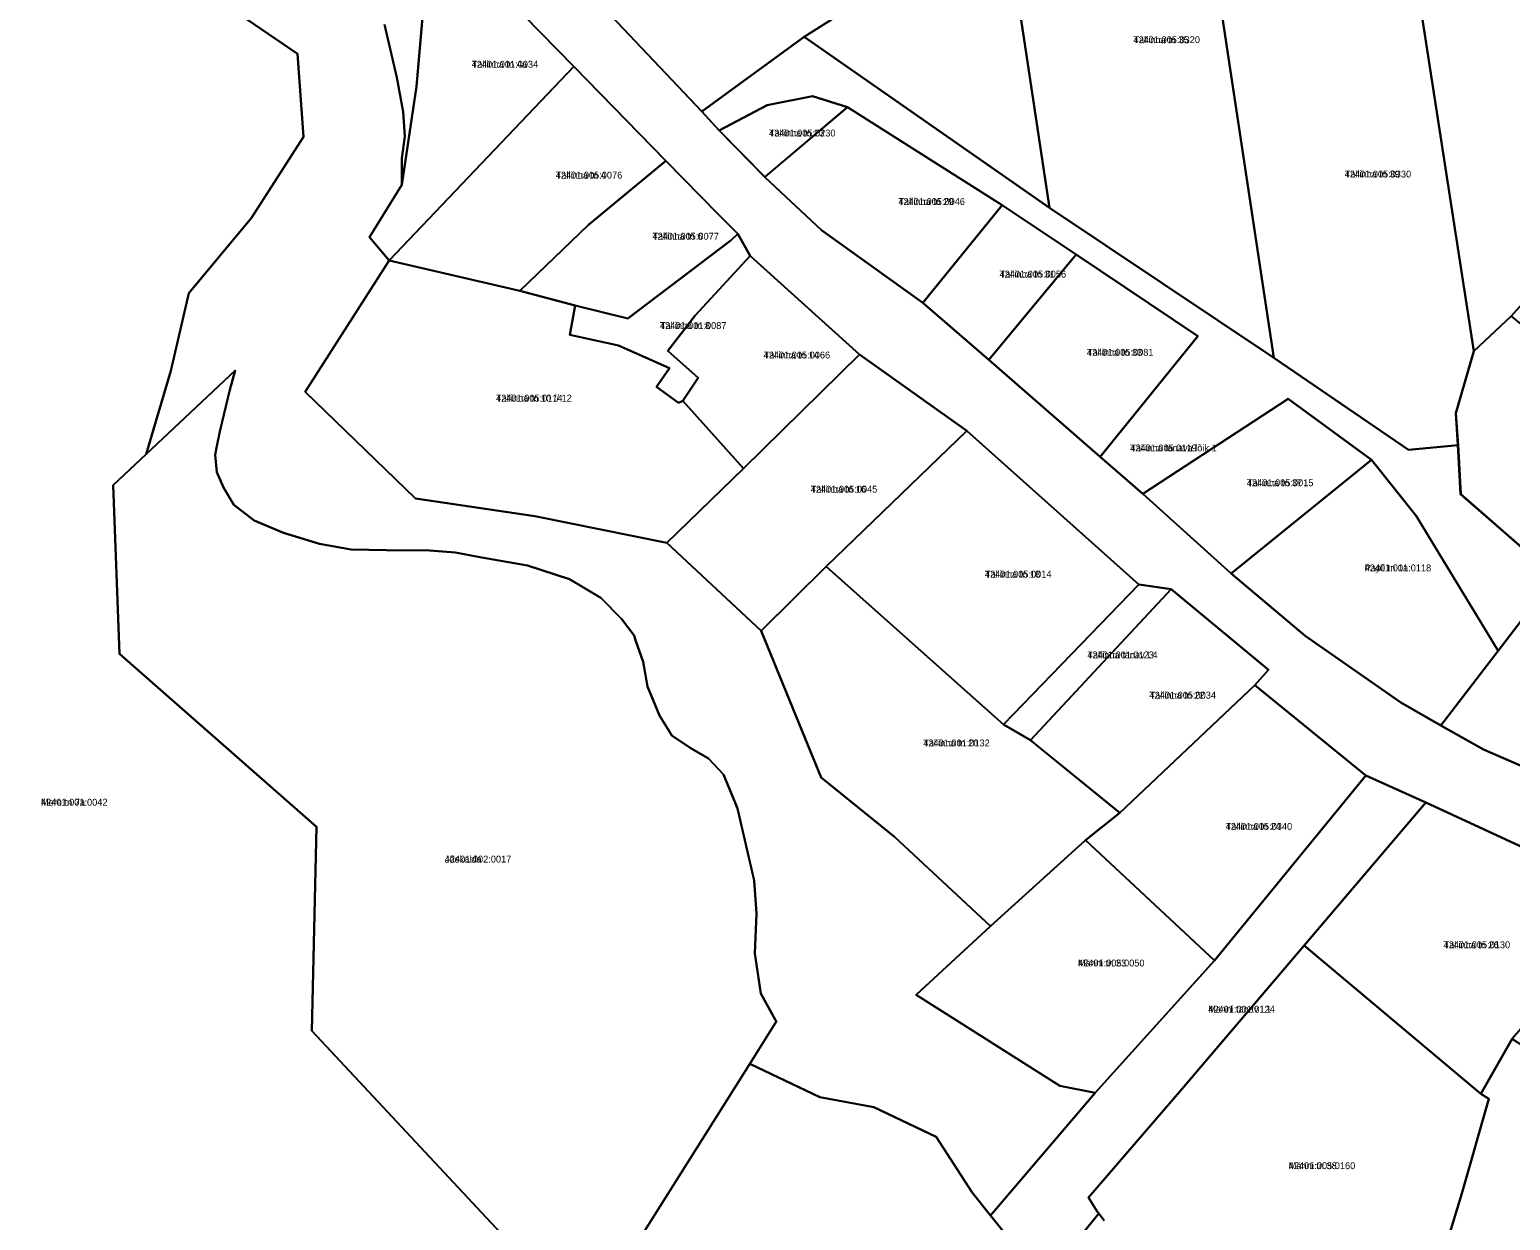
# Model space of a CAD drawing. Extents: x 595979 to 597983, y 6604231 to 6607350.
# Drawn here: x 596873.6 to 597196.3, y 6606049.7 to 6606309.2 of the extents above; entities that cross this region are included whole.
import ezdxf

# ---------------------------------------------------------------- set-up
doc = ezdxf.new("R2010")
doc.units = 0
for name, color, linetype in [('L_AADRESS', 7, 'Continuous'), ('PIIR', 7, 'Continuous'), ('TUNNUS', 7, 'Continuous')]:
    doc.layers.add(name, color=color, linetype=linetype)

msp = doc.modelspace()

# ---------------------------------------------------------------- linework, layer by layer
at = {"layer": 'PIIR'}
for points in [[(596834.39, 6606472.9), (596889.22, 6606422.58), (596903.83, 6606409.45), (596924.96, 6606390.98), (596925.76, 6606392.61), (596951.48, 6606366.75), (597000.4, 6606312.1), (597020.14, 6606291.3), (597023.9, 6606287.2), (597033.87, 6606277.01), (597046.17, 6606265.47), (597068.29, 6606249.61), (597082.64, 6606237.21), (597106.96, 6606216.02), (597116.23, 6606207.98), (597135.48, 6606190.61), (597151.62, 6606177.02), (597172.5, 6606162.53), (597181.22, 6606157.49), (597190.5, 6606152.27), (597213.06, 6606142.48)], [(597335.48, 6606042.99), (597280.71, 6606085.45), (597282.61, 6606087.75), (597275.71, 6606093.22), (597238.19, 6606110.46), (597218.63, 6606121.93), (597177.93, 6606140.7), (597164.82, 6606146.62), (597140.63, 6606166.31), (597143.65, 6606169.64), (597122.43, 6606187.25), (597115.38, 6606188.24), (597077.86, 6606221.72), (597054.46, 6606238.34), (597030.62, 6606259.83), (597027.93, 6606264.63), (597023.69, 6606268.92), (597012.28, 6606280.57), (596992.17, 6606301.13), (596970.33, 6606323.53), (596967.59, 6606326.51), (596937.54, 6606358.48), (596909.1, 6606385.61), (596872.46, 6606418.2)], [(596873.07, 6606344.89), (596880.13, 6606332.1), (596892.53, 6606323.5), (596909.78, 6606319.05), (596932, 6606303.91), (596933.31, 6606285.77), (596921.98, 6606268.12), (596908.32, 6606251.69), (596904.39, 6606234.77), (596898.95, 6606216.64), (596891.77, 6606209.88), (596893.14, 6606173.15), (596936.13, 6606135.39), (596935.06, 6606090.99), (596994.79, 6606027), (597030.56, 6606083.77), (597045.82, 6606076.48), (597057.63, 6606074.35), (597071.17, 6606067.83), (597079.05, 6606055.73), (597083.05, 6606050.71), (597087.59, 6606045.02)], [(596950.93, 6606310.3), (596953.65, 6606298.71), (596954.98, 6606291.24), (596955.37, 6606285.85), (596954.7, 6606281.05), (596954.68, 6606275.37), (596947.69, 6606263.93), (596951.96, 6606258.85), (596933.62, 6606230.19), (596957.72, 6606206.99), (596983.69, 6606203.12), (597012.49, 6606197.32), (597033.02, 6606178.16), (597043.27, 6606153.07), (597046.13, 6606146.19), (597062.08, 6606133.26), (597083.01, 6606113.76), (597066.84, 6606098.82), (597098.16, 6606079), (597105.86, 6606077.47), (597083.05, 6606050.71), (597079.05, 6606055.73), (597071.17, 6606067.83), (597057.63, 6606074.35), (597045.82, 6606076.48), (597030.56, 6606083.77), (597036.36, 6606093.06), (597036.13, 6606093.31), (597032.94, 6606099.07), (597031.67, 6606107.78), (597032.05, 6606116.51), (597031.52, 6606123.69), (597027.9, 6606139.39), (597027.43, 6606140.52), (597024.83, 6606146.83), (597021.57, 6606150.34), (597017.53, 6606152.66), (597013.58, 6606155.32), (597010.9, 6606159.68), (597008.29, 6606166), (597007.3, 6606171.36), (597005.68, 6606176.09), (597005.34, 6606177.09), (597002.57, 6606180.72), (596998.06, 6606185.33), (596991.26, 6606189.4), (596982.11, 6606192.38), (596971.71, 6606194.21), (596966.43, 6606195.17), (596960.73, 6606195.61), (596951.39, 6606195.71), (596943.65, 6606195.88), (596936.74, 6606197.09), (596928.94, 6606199.52), (596922.53, 6606202.21), (596918.12, 6606205.57), (596915.85, 6606209.34), (596914.36, 6606212.75), (596913.99, 6606216.52), (596914.38, 6606218.38), (596915.05, 6606221.56), (596917.23, 6606230.64), (596918.35, 6606234.87), (596898.95, 6606216.64), (596904.39, 6606234.77), (596908.32, 6606251.69), (596921.98, 6606268.12), (596933.31, 6606285.77), (596932, 6606303.91), (596909.78, 6606319.05)], [(596959.9, 6606319.46), (596957.88, 6606296.75), (596954.68, 6606275.37), (596954.7, 6606281.05), (596955.37, 6606285.85), (596954.98, 6606291.24), (596953.65, 6606298.71), (596950.93, 6606310.3)], [(597213.06, 6606142.48), (597190.5, 6606152.27), (597181.22, 6606157.49), (597193.69, 6606173.74), (597200.61, 6606182.75)], [(597107.82, 6606049.61), (597106.24, 6606051.6), (597104.42, 6606054.65), (597124.7, 6606078.28), (597151.41, 6606109.53), (597189.92, 6606077.21), (597191.64, 6606076.17), (597185.75, 6606055.52), (597179.95, 6606036.42)], [(597179.95, 6606036.42), (597185.75, 6606055.52), (597191.64, 6606076.17), (597189.92, 6606077.21), (597196.74, 6606089.23), (597230.52, 6606067.35), (597250.21, 6606054.1), (597275.71, 6606093.22), (597282.61, 6606087.75), (597280.71, 6606085.45), (597335.48, 6606042.99)], [(597092.26, 6606033.51), (597106.61, 6606051.14), (597107.82, 6606049.61)]]:
    msp.add_lwpolyline(points, dxfattribs=at)
for points in [[(597080.06, 6606377.03), (597162.42, 6606404.24), (597160.2, 6606410.55), (597171.57, 6606414.32), (597187.46, 6606362.63), (597186.67, 6606356.79), (597201.01, 6606313.35), (597238.31, 6606326.16), (597250.13, 6606310.53), (597231.9, 6606292.55), (597234.92, 6606289.4), (597221.43, 6606274.46), (597196.48, 6606246.74), (597188.4, 6606239.05), (597174.43, 6606329.25), (597132.04, 6606321.84), (597126.69, 6606355.35), (597083.62, 6606351.85)], [(597041.83, 6606371.12), (597046.38, 6606375), (597053.14, 6606379.98), (597063.03, 6606383.44), (597066.89, 6606372.38), (597072.74, 6606374.35), (597080.06, 6606377.03), (597083.62, 6606351.85), (597095.88, 6606270.34), (597042.44, 6606307.62), (597050.51, 6606312.65), (597036.88, 6606340.6), (597035.11, 6606345.68), (597031.22, 6606354.38)], [(597017.42, 6606344.12), (597020.65, 6606343.19), (597023.67, 6606343.83), (597031.22, 6606354.38), (597035.11, 6606345.68), (597036.88, 6606340.6), (597050.51, 6606312.65), (597042.44, 6606307.62), (597020.14, 6606291.3), (597000.4, 6606312.1), (597006.05, 6606317.27)], [(597083.62, 6606351.85), (597126.69, 6606355.35), (597132.04, 6606321.84), (597144.75, 6606237.64), (597095.88, 6606270.34)], [(597174.43, 6606329.25), (597188.4, 6606239.05), (597184.43, 6606225.56), (597184.95, 6606218.63), (597174.17, 6606217.61), (597144.75, 6606237.64), (597132.04, 6606321.84)], [(596992.17, 6606301.13), (596951.96, 6606258.85), (596947.69, 6606263.93), (596954.68, 6606275.37), (596957.88, 6606296.75), (596959.9, 6606319.46), (596967.59, 6606326.51), (596970.33, 6606323.53)], [(597020.14, 6606291.3), (597042.44, 6606307.62), (597095.88, 6606270.34), (597144.75, 6606237.64), (597174.17, 6606217.61), (597184.95, 6606218.63), (597185.55, 6606207.91), (597206.83, 6606189.31), (597200.61, 6606182.75), (597193.69, 6606173.74), (597175.79, 6606203.2), (597166.08, 6606215.39), (597147.91, 6606228.72), (597116.23, 6606207.98), (597106.96, 6606216.02), (597128.2, 6606242.38), (597101.7, 6606260.14), (597085.57, 6606270.92), (597051.85, 6606292.26), (597044.2, 6606294.68), (597034.37, 6606292.71), (597023.9, 6606287.2)], [(596992.17, 6606301.13), (597012.28, 6606280.57), (596995.39, 6606266.59), (596980.45, 6606252.25), (596951.96, 6606258.85)], [(597023.9, 6606287.2), (597034.37, 6606292.71), (597044.2, 6606294.68), (597051.85, 6606292.26), (597033.82, 6606277.06)], [(597033.87, 6606277.01), (597051.85, 6606292.26), (597085.57, 6606270.92), (597068.29, 6606249.61), (597046.17, 6606265.47)], [(597012.28, 6606280.57), (597023.69, 6606268.92), (597027.93, 6606264.63), (597026.5, 6606263.28), (597003.99, 6606246.18), (596992.49, 6606249.01), (596980.45, 6606252.25), (596995.39, 6606266.59)], [(597068.29, 6606249.61), (597085.57, 6606270.92), (597101.7, 6606260.14), (597082.64, 6606237.21)], [(597026.5, 6606263.28), (597027.93, 6606264.63), (597030.62, 6606259.83), (597018.68, 6606246.89), (597012.67, 6606239.17), (597019.34, 6606233.27), (597015.94, 6606228.27), (597015.04, 6606227.84), (597010.22, 6606231.32), (597013.09, 6606235.4), (597001.96, 6606240.31), (596991.33, 6606242.64), (596992.49, 6606249.01), (597003.99, 6606246.18)], [(596951.96, 6606258.85), (596980.45, 6606252.25), (596992.49, 6606249.01), (596991.33, 6606242.64), (597001.96, 6606240.31), (597013.09, 6606235.4), (597010.22, 6606231.32), (597015.04, 6606227.84), (597015.94, 6606228.27), (597029.2, 6606213.51), (597012.49, 6606197.32), (596983.69, 6606203.12), (596957.72, 6606206.99), (596933.62, 6606230.19)], [(597030.62, 6606259.83), (597054.46, 6606238.34), (597029.2, 6606213.51), (597015.94, 6606228.27), (597019.34, 6606233.27), (597012.67, 6606239.17), (597018.68, 6606246.89)], [(597082.64, 6606237.21), (597101.7, 6606260.14), (597128.2, 6606242.38), (597106.96, 6606216.02)], [(597188.4, 6606239.05), (597196.48, 6606246.74), (597232.45, 6606216.97), (597206.83, 6606189.31), (597185.49, 6606207.93), (597184.91, 6606218.64), (597184.43, 6606225.56)], [(597077.86, 6606221.72), (597047.21, 6606192.13), (597033.02, 6606178.16), (597012.49, 6606197.32), (597029.2, 6606213.51), (597054.46, 6606238.34)], [(596918.35, 6606234.87), (596917.23, 6606230.64), (596915.05, 6606221.56), (596914.38, 6606218.38), (596913.99, 6606216.52), (596914.36, 6606212.75), (596915.85, 6606209.34), (596918.12, 6606205.57), (596922.53, 6606202.21), (596928.94, 6606199.52), (596936.74, 6606197.09), (596943.65, 6606195.88), (596951.39, 6606195.71), (596960.73, 6606195.61), (596966.43, 6606195.17), (596971.71, 6606194.21), (596982.11, 6606192.38), (596991.26, 6606189.4), (596998.06, 6606185.33), (597002.57, 6606180.72), (597005.34, 6606177.09), (597005.68, 6606176.09), (597007.3, 6606171.36), (597008.29, 6606166), (597010.9, 6606159.68), (597013.58, 6606155.32), (597017.53, 6606152.66), (597021.57, 6606150.34), (597024.83, 6606146.83), (597027.43, 6606140.52), (597027.9, 6606139.39), (597031.52, 6606123.69), (597032.05, 6606116.51), (597031.67, 6606107.78), (597032.94, 6606099.07), (597036.13, 6606093.31), (597036.36, 6606093.06), (597030.56, 6606083.77), (596994.79, 6606027), (596935.06, 6606090.99), (596936.13, 6606135.39), (596893.14, 6606173.15), (596891.77, 6606209.88), (596898.95, 6606216.64)], [(597116.23, 6606207.98), (597147.91, 6606228.72), (597166.08, 6606215.39), (597135.48, 6606190.61)], [(597047.21, 6606192.13), (597077.86, 6606221.72), (597115.38, 6606188.24), (597085.84, 6606157.73), (597083.24, 6606160.07)], [(597181.22, 6606157.49), (597172.5, 6606162.53), (597151.62, 6606177.02), (597135.48, 6606190.61), (597166.08, 6606215.39), (597175.79, 6606203.2), (597193.69, 6606173.74)], [(597047.21, 6606192.13), (597083.24, 6606160.07), (597085.84, 6606157.73), (597091.71, 6606154.31), (597093.16, 6606153.13), (597111.24, 6606138.47), (597103.74, 6606132.5), (597083.01, 6606113.76), (597062.08, 6606133.26), (597046.13, 6606146.19), (597043.27, 6606153.07), (597033.02, 6606178.16)], [(597122.43, 6606187.25), (597091.71, 6606154.31), (597085.84, 6606157.73), (597115.38, 6606188.24)], [(597122.43, 6606187.25), (597143.65, 6606169.64), (597140.63, 6606166.31), (597111.24, 6606138.47), (597091.71, 6606154.31)], [(597111.24, 6606138.47), (597140.63, 6606166.31), (597164.82, 6606146.62), (597131.85, 6606106.28), (597103.74, 6606132.5)], [(597092.26, 6606033.51), (597089.62, 6606038.98), (597087.59, 6606045.02), (597083.05, 6606050.71), (597105.86, 6606077.47), (597131.85, 6606106.28), (597164.82, 6606146.62), (597177.93, 6606140.7), (597151.41, 6606109.53), (597124.7, 6606078.28), (597104.42, 6606054.65), (597106.24, 6606051.6), (597106.61, 6606051.14)], [(597177.93, 6606140.7), (597218.63, 6606121.93), (597207.27, 6606101.31), (597196.74, 6606089.23), (597189.92, 6606077.21), (597151.41, 6606109.53)], [(597083.01, 6606113.76), (597103.74, 6606132.5), (597131.85, 6606106.28), (597105.86, 6606077.47), (597098.16, 6606079), (597066.84, 6606098.82)]]:
    msp.add_lwpolyline(points, close=True, dxfattribs=at)

# ---------------------------------------------------------------- texts
at = {"layer": 'L_AADRESS'}
for s, p in [('Tallinna tn 35', (597114.18, 6606306.21)), ('Tallinna tn 4a', (596969.93, 6606300.86)), ('Tallinna tn 23', (597034.74, 6606285.87)), ('Tallinna tn 4', (596988.26, 6606276.69)), ('Tallinna tn 39', (597160.22, 6606276.94)), ('Tallinna tn 29', (597062.95, 6606270.94)), ('Tallinna tn 6', (597009.32, 6606263.38)), ('Tallinna tn 31', (597085, 6606255.13)), ('Tallinna tn 8', (597010.97, 6606243.91)), ('Tallinna tn 14', (597033.57, 6606237.49)), ('Tallinna tn 33', (597104.05, 6606238.08)), ('Tallinna tn 10 // 12', (596975.25, 6606228.09)), ('Tallinna tänava lõik 1', (597113.48, 6606217.24)), ('Tallinna tn 16', (597043.84, 6606208.25)), ('Tallinna tn 37', (597138.91, 6606209.66)), ('Tallinna tn 18', (597081.81, 6606189.73)), ('Papli tn 1a', (597164.58, 6606191.1)), ('Tallinna tänav L4', (597104.14, 6606172.13)), ('Tallinna tn 22', (597117.68, 6606163.36)), ('Tallinna tn 20', (597068.36, 6606152.95)), ('Mere tn 7a', (596876.06, 6606140.03)), ('Tallinna tn 24', (597134.28, 6606134.77)), ('Jõekalda', (596964.07, 6606127.63)), ('Tallinna tn 26', (597181.79, 6606108.96)), ('Männi tn 23', (597102.1, 6606104.99)), ('Männi tänav L1', (597130.49, 6606094.91)), ('Männi tn 38', (597148.03, 6606060.82))]:
    msp.add_text(s, height=1.5, dxfattribs=at).set_placement(p)
at = {"layer": 'TUNNUS'}
for s, p in [('42401:005:0320', (597114.18, 6606306.21)), ('42401:001:0034', (596969.93, 6606300.86)), ('42401:005:0230', (597034.74, 6606285.87)), ('42401:005:0076', (596988.26, 6606276.69)), ('42401:005:0330', (597160.22, 6606276.94)), ('42401:005:0046', (597062.95, 6606270.94)), ('42401:005:0077', (597009.32, 6606263.38)), ('42401:005:0056', (597085, 6606255.13)), ('42401:001:0087', (597010.97, 6606243.91)), ('42401:005:0066', (597033.57, 6606237.49)), ('42401:005:0081', (597104.05, 6606238.08)), ('42401:005:0114', (596975.25, 6606228.09)), ('42401:005:0119', (597113.48, 6606217.24)), ('42401:005:0045', (597043.84, 6606208.25)), ('42401:005:0015', (597138.91, 6606209.66)), ('42401:005:0014', (597081.81, 6606189.73)), ('42401:001:0118', (597164.58, 6606191.1)), ('42401:001:0123', (597104.14, 6606172.13)), ('42401:005:0034', (597117.68, 6606163.36)), ('42401:001:0132', (597068.36, 6606152.95)), ('42401:001:0042', (596876.06, 6606140.03)), ('42401:005:0340', (597134.28, 6606134.77)), ('42401:002:0017', (596964.07, 6606127.63)), ('42401:005:0130', (597181.79, 6606108.96)), ('42401:005:0050', (597102.1, 6606104.99)), ('42401:001:0124', (597130.49, 6606094.91)), ('42401:005:0160', (597148.03, 6606060.82))]:
    msp.add_text(s, height=1.5, dxfattribs=at).set_placement(p)

doc.saveas('drawing.dxf')
